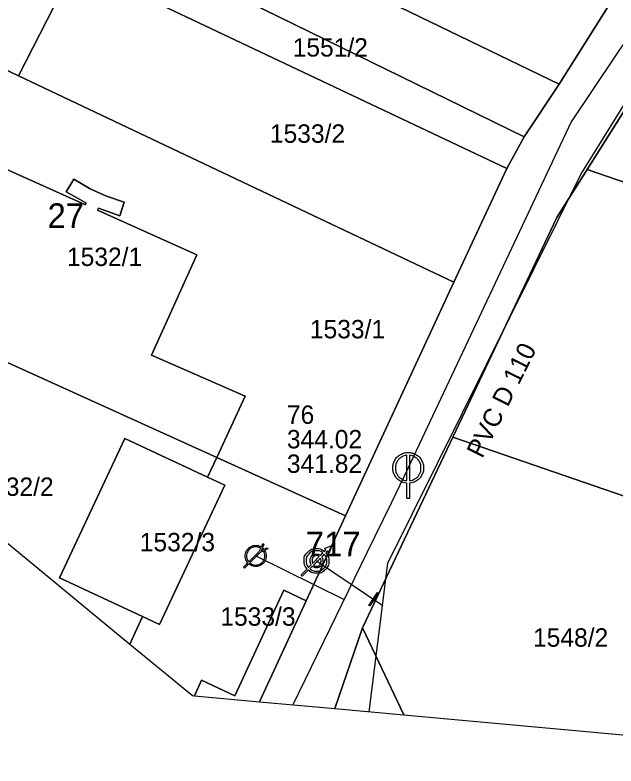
# Model space of a CAD drawing. Extents: x -559813 to -559493, y -1075874 to -1075701.
# Drawn here: x -559758.6 to -559709.6, y -1075858.6 to -1075797.4 of the extents above; entities that cross this region are included whole.
import ezdxf

# ---------------------------------------------------------------- set-up
doc = ezdxf.new("R2010")
doc.units = 0
for name, color, linetype in [('Adresní místo-text', 7, 'Continuous'), ('Armatura vodovodní', 7, 'Continuous'), ('Default', 7, 'Continuous'), ('Kanalizační přípojka', 7, 'Continuous'), ('Kanalizační stoka', 7, 'Continuous'), ('Kanalizační šachta', 7, 'Continuous'), ('Odběrné místo', 7, 'Continuous'), ('Odběrné místo na kanalizaci', 7, 'Continuous'), ('Parcela-polygon', 7, 'Continuous'), ('Parcela-text', 7, 'Continuous'), ('Popis šachty', 7, 'Continuous'), ('Vodovodní přípojka', 7, 'Continuous'), ('Vodovodní řad', 7, 'Continuous'), ('Řad vodovodní popis', 7, 'Continuous')]:
    doc.layers.add(name, color=color, linetype=linetype)

msp = doc.modelspace()

# ---------------------------------------------------------------- linework, layer by layer
at = {"layer": 'Armatura vodovodní'}
msp.add_lwpolyline([(-559729.021, -1075844.533), (-559729.716, -1075845.572), (-559729.781, -1075845.528), (-559729.086, -1075844.49), (-559729.021, -1075844.533)], dxfattribs=at)
at = {"layer": 'Default'}
for points, degree in [([(-559726.683, -1075835.568), (-559726.941, -1075835.55), (-559727.203, -1075835.404), (-559727.5, -1075835.24), (-559727.665, -1075834.943), (-559727.83, -1075834.645), (-559727.83, -1075834.32), (-559727.83, -1075833.993), (-559727.662, -1075833.693), (-559727.493, -1075833.392), (-559727.195, -1075833.231), (-559726.897, -1075833.07), (-559726.58, -1075833.07), (-559726.265, -1075833.07), (-559725.966, -1075833.231), (-559725.667, -1075833.392), (-559725.498, -1075833.693), (-559725.33, -1075833.993), (-559725.33, -1075834.32), (-559725.33, -1075834.645), (-559725.495, -1075834.943), (-559725.66, -1075835.24), (-559725.957, -1075835.404), (-559726.219, -1075835.55), (-559726.477, -1075835.568)], 3), ([(-559726.683, -1075833.282), (-559726.88, -1075833.299), (-559727.095, -1075833.414), (-559727.344, -1075833.549), (-559727.483, -1075833.799), (-559727.622, -1075834.049), (-559727.622, -1075834.32), (-559727.622, -1075834.591), (-559727.486, -1075834.838), (-559727.349, -1075835.084), (-559727.1, -1075835.221), (-559726.888, -1075835.341), (-559726.683, -1075835.355)], 3), ([(-559726.477, -1075835.355), (-559726.272, -1075835.341), (-559726.058, -1075835.221), (-559725.811, -1075835.084), (-559725.674, -1075834.838), (-559725.538, -1075834.591), (-559725.538, -1075834.32), (-559725.538, -1075834.049), (-559725.678, -1075833.799), (-559725.818, -1075833.549), (-559726.067, -1075833.414), (-559726.28, -1075833.299), (-559726.477, -1075833.282)], 3), ([(-559739.665, -1075842.056), (-559739.716, -1075841.995), (-559739.756, -1075841.921), (-559739.87, -1075841.718), (-559739.87, -1075841.496), (-559739.87, -1075841.273), (-559739.755, -1075841.067), (-559739.64, -1075840.862), (-559739.436, -1075840.752), (-559739.232, -1075840.641), (-559739.015, -1075840.641), (-559738.8, -1075840.641), (-559738.596, -1075840.752), (-559738.577, -1075840.762), (-559738.558, -1075840.774)], 3), ([(-559738.609, -1075840.874), (-559738.629, -1075840.861), (-559738.651, -1075840.849), (-559738.829, -1075840.753), (-559739.015, -1075840.753), (-559739.203, -1075840.753), (-559739.38, -1075840.849), (-559739.558, -1075840.945), (-559739.658, -1075841.124), (-559739.757, -1075841.302), (-559739.757, -1075841.496), (-559739.757, -1075841.689), (-559739.659, -1075841.865), (-559739.626, -1075841.924), (-559739.583, -1075841.975)], 3), ([(-559738.294, -1075841.037), (-559738.286, -1075841.051), (-559738.276, -1075841.067), (-559738.161, -1075841.273), (-559738.161, -1075841.496), (-559738.161, -1075841.718), (-559738.273, -1075841.921), (-559738.386, -1075842.125), (-559738.59, -1075842.237), (-559738.793, -1075842.35), (-559739.015, -1075842.35), (-559739.237, -1075842.35), (-559739.44, -1075842.237), (-559739.514, -1075842.197), (-559739.577, -1075842.144)], 3), ([(-559738.464, -1075840.995), (-559738.489, -1075840.968), (-559738.514, -1075840.945)], 2), ([(-559738.463, -1075840.841), (-559738.408, -1075840.887), (-559738.361, -1075840.944)], 2), ([(-559734.832, -1075842.561), (-559735.073, -1075842.284), (-559735.073, -1075841.908), (-559735.073, -1075841.491), (-559734.778, -1075841.196), (-559734.482, -1075840.901), (-559734.063, -1075840.901), (-559733.689, -1075840.901), (-559733.413, -1075841.138)], 3), ([(-559733.531, -1075841.257), (-559733.758, -1075841.068), (-559734.063, -1075841.068), (-559734.413, -1075841.068), (-559734.659, -1075841.314), (-559734.904, -1075841.56), (-559734.904, -1075841.908), (-559734.904, -1075842.215), (-559734.713, -1075842.442)], 3), ([(-559739.496, -1075842.063), (-559739.445, -1075842.106), (-559739.384, -1075842.139), (-559739.207, -1075842.238), (-559739.015, -1075842.238), (-559738.823, -1075842.238), (-559738.646, -1075842.14), (-559738.469, -1075842.042), (-559738.371, -1075841.865), (-559738.273, -1075841.689), (-559738.273, -1075841.496), (-559738.273, -1075841.302), (-559738.373, -1075841.124), (-559738.383, -1075841.105), (-559738.394, -1075841.088)], 3), ([(-559733.305, -1075841.244), (-559733.055, -1075841.525), (-559733.055, -1075841.908), (-559733.055, -1075842.326), (-559733.351, -1075842.62), (-559733.646, -1075842.915), (-559734.063, -1075842.915), (-559734.447, -1075842.915), (-559734.726, -1075842.669)], 3), ([(-559734.607, -1075842.549), (-559734.377, -1075842.747), (-559734.063, -1075842.747), (-559733.716, -1075842.747), (-559733.469, -1075842.501), (-559733.222, -1075842.256), (-559733.222, -1075841.908), (-559733.222, -1075841.594), (-559733.424, -1075841.364)], 3), ([(-559734.493, -1075842.221), (-559734.502, -1075842.205), (-559734.509, -1075842.189), (-559734.571, -1075842.062), (-559734.571, -1075841.92), (-559734.571, -1075841.653), (-559734.427, -1075841.502), (-559734.283, -1075841.35), (-559734.056, -1075841.35), (-559733.908, -1075841.35), (-559733.789, -1075841.421), (-559733.759, -1075841.439), (-559733.734, -1075841.46)], 3), ([(-559733.828, -1075841.554), (-559733.845, -1075841.539), (-559733.864, -1075841.527), (-559733.95, -1075841.474), (-559734.056, -1075841.474), (-559734.206, -1075841.474), (-559734.316, -1075841.577), (-559734.425, -1075841.68), (-559734.425, -1075841.923), (-559734.425, -1075842.034), (-559734.391, -1075842.118)], 3), ([(-559733.633, -1075841.572), (-559733.618, -1075841.596), (-559733.606, -1075841.62), (-559733.543, -1075841.747), (-559733.543, -1075841.908), (-559733.543, -1075842.072), (-559733.609, -1075842.2), (-559733.675, -1075842.329), (-559733.796, -1075842.396), (-559733.917, -1075842.462), (-559734.057, -1075842.462), (-559734.209, -1075842.462), (-559734.328, -1075842.389), (-559734.365, -1075842.366), (-559734.397, -1075842.339)], 3), ([(-559734.304, -1075842.245), (-559734.204, -1075842.34), (-559734.059, -1075842.34), (-559733.897, -1075842.34), (-559733.794, -1075842.227), (-559733.69, -1075842.114), (-559733.69, -1075841.907), (-559733.69, -1075841.776), (-559733.734, -1075841.679), (-559733.735, -1075841.677), (-559733.735, -1075841.676)], 3)]:
    msp.add_open_spline(points, degree=degree, dxfattribs=at)
at = {"layer": 'Kanalizační přípojka'}
msp.add_lwpolyline([(-559739.016, -1075841.496), (-559731.811, -1075845.058)], dxfattribs=at)
at = {"layer": 'Kanalizační stoka'}
for points in [[(-559704.486, -1075792.979), (-559709.634, -1075800.651)], [(-559709.634, -1075800.651), (-559713.29, -1075806.1)], [(-559713.29, -1075806.1), (-559726.58, -1075834.32)], [(-559726.58, -1075834.32), (-559727.976, -1075837.185)], [(-559727.976, -1075837.185), (-559729.959, -1075841.256)], [(-559729.959, -1075841.256), (-559735.99, -1075853.634)]]:
    msp.add_lwpolyline(points, dxfattribs=at)
at = {"layer": 'Kanalizační šachta'}
for points in [[(-559726.683, -1075835.355), (-559726.683, -1075833.282)], [(-559726.477, -1075833.282), (-559726.477, -1075835.355)], [(-559726.477, -1075835.568), (-559726.477, -1075836.82), (-559726.683, -1075836.82), (-559726.683, -1075835.568)]]:
    msp.add_lwpolyline(points, dxfattribs=at)
at = {"layer": 'Odběrné místo'}
for points in [[(-559733.413, -1075841.138), (-559733.285, -1075841.01)], [(-559733.285, -1075841.01), (-559733.403, -1075840.899), (-559732.816, -1075840.658), (-559733.038, -1075841.244), (-559733.175, -1075841.115), (-559733.305, -1075841.244)], [(-559734.391, -1075842.118), (-559733.828, -1075841.554)], [(-559733.735, -1075841.676), (-559734.304, -1075842.245)], [(-559733.734, -1075841.46), (-559733.531, -1075841.257)], [(-559733.424, -1075841.364), (-559733.633, -1075841.572)], [(-559734.713, -1075842.442), (-559734.493, -1075842.221)], [(-559734.726, -1075842.669), (-559735.215, -1075843.158), (-559735.316, -1075843.046), (-559734.832, -1075842.561)], [(-559734.397, -1075842.339), (-559734.607, -1075842.549)]]:
    msp.add_lwpolyline(points, dxfattribs=at)
at = {"layer": 'Odběrné místo na kanalizaci'}
for points in [[(-559739.583, -1075841.975), (-559738.741, -1075841.131), (-559738.609, -1075840.874)], [(-559738.514, -1075840.945), (-559738.563, -1075841.044), (-559738.464, -1075840.995)], [(-559738.558, -1075840.774), (-559738.548, -1075840.755), (-559738.502, -1075840.637), (-559738.442, -1075840.496), (-559738.341, -1075840.542), (-559738.407, -1075840.703), (-559738.455, -1075840.823), (-559738.463, -1075840.841)], [(-559738.361, -1075840.944), (-559738.343, -1075840.935), (-559738.222, -1075840.887), (-559738.072, -1075840.826), (-559738.016, -1075840.92), (-559738.158, -1075840.982), (-559738.276, -1075841.027), (-559738.294, -1075841.037)], [(-559738.394, -1075841.088), (-559738.655, -1075841.222), (-559739.496, -1075842.063)], [(-559739.577, -1075842.144), (-559739.588, -1075842.156), (-559739.678, -1075842.246), (-559739.93, -1075842.497), (-559740.018, -1075842.408), (-559739.766, -1075842.157), (-559739.676, -1075842.068), (-559739.665, -1075842.056)]]:
    msp.add_lwpolyline(points, dxfattribs=at)
at = {"layer": 'Parcela-polygon'}
for p, q in [((-559778.194, -1075824.865), (-559749.276, -1075848.685)), ((-559744.017, -1075852.905), (-559738.719, -1075853.386)), ((-559738.719, -1075853.386), (-559732.551, -1075853.947)), ((-559732.551, -1075853.947), (-559726.935, -1075854.457)), ((-559726.935, -1075854.457), (-559706.34, -1075856.328))]:
    msp.add_line(p, q, dxfattribs=at)
for points in [[(-559732.551, -1075853.947), (-559730.31, -1075847.37), (-559722.94, -1075831.81), (-559714.46, -1075813.89), (-559711.98, -1075809.97), (-559705.24, -1075799.29), (-559698.1, -1075787.99), (-559694.39, -1075782.11), (-559686.19, -1075769.14), (-559684.4, -1075766.45), (-559674.88, -1075752.15), (-559667.58, -1075740.58), (-559681.23, -1075754.03), (-559700.36, -1075780.95), (-559706.7, -1075791.01), (-559714.26, -1075803.02), (-559717.12, -1075807.32), (-559718.54, -1075809.9), (-559722.85, -1075819.18), (-559731.69, -1075838.23), (-559734.91, -1075845.17), (-559738.719, -1075853.386)], [(-559812.545, -1075795.607), (-559773.1, -1075813.33), (-559769.59, -1075805.38), (-559766.53, -1075798.46), (-559758.36, -1075802.33), (-559753.71, -1075793.22), (-559762.4, -1075789.09), (-559800.612, -1075773.14)], [(-559749.276, -1075848.685), (-559748.24, -1075846.45), (-559755.02, -1075843.27), (-559749.7, -1075831.92), (-559742.95, -1075835.07), (-559742.2, -1075833.46), (-559775.35, -1075818.43), (-559778.194, -1075824.865)], [(-559681.019, -1075858.629), (-559676.66, -1075847.75), (-559722.94, -1075831.81), (-559730.31, -1075847.37), (-559726.935, -1075854.457)], [(-559744.017, -1075852.905), (-559743.43, -1075851.64), (-559740.72, -1075852.91), (-559736.71, -1075844.29), (-559734.91, -1075845.17), (-559731.69, -1075838.23), (-559742.2, -1075833.46), (-559742.95, -1075835.07), (-559741.54, -1075835.73), (-559746.86, -1075847.1), (-559748.24, -1075846.45), (-559749.276, -1075848.685)], [(-559738.719, -1075853.386), (-559734.91, -1075845.17), (-559736.71, -1075844.29), (-559740.72, -1075852.91), (-559743.43, -1075851.64), (-559744.017, -1075852.905)], [(-559726.935, -1075854.457), (-559730.31, -1075847.37), (-559732.551, -1075853.947)], [(-559749.276, -1075848.685), (-559744.17, -1075852.891), (-559744.017, -1075852.905)]]:
    msp.add_lwpolyline(points, dxfattribs=at)
for points in [[(-559737.63, -1075771.45), (-559743.97, -1075773.56), (-559749.98, -1075785.74), (-559714.26, -1075803.02), (-559706.7, -1075791.01), (-559707.59, -1075786.09)], [(-559749.98, -1075785.74), (-559752.15, -1075790.16), (-559717.12, -1075807.32), (-559714.26, -1075803.02)], [(-559717.12, -1075807.32), (-559752.15, -1075790.16), (-559753.71, -1075793.22), (-559718.54, -1075809.9)], [(-559753.71, -1075793.22), (-559758.36, -1075802.33), (-559722.85, -1075819.18), (-559718.54, -1075809.9)], [(-559752.88, -1075812.71), (-559754.47, -1075811.8), (-559753.84, -1075810.76), (-559752.51, -1075811.55), (-559751.19, -1075812.16), (-559749.74, -1075812.64), (-559750.1, -1075813.77), (-559751.85, -1075813.14), (-559751.91, -1075813.31), (-559743.83, -1075816.93), (-559747.51, -1075825.13), (-559739.88, -1075828.47), (-559742.2, -1075833.46), (-559731.69, -1075838.23), (-559722.85, -1075819.18), (-559758.36, -1075802.33), (-559766.53, -1075798.46), (-559769.59, -1075805.38), (-559760.42, -1075809.49), (-559752.91, -1075812.86)], [(-559705.24, -1075799.29), (-559711.98, -1075809.97), (-559671.09, -1075824.05), (-559664.87, -1075813.06)], [(-559760.42, -1075809.49), (-559769.59, -1075805.38), (-559773.1, -1075813.33), (-559775.35, -1075818.43), (-559742.2, -1075833.46), (-559739.88, -1075828.47), (-559747.51, -1075825.13), (-559743.83, -1075816.93), (-559751.91, -1075813.31), (-559751.85, -1075813.14), (-559750.1, -1075813.77), (-559749.74, -1075812.64), (-559751.19, -1075812.16), (-559752.51, -1075811.55), (-559753.84, -1075810.76), (-559754.47, -1075811.8), (-559752.88, -1075812.71), (-559752.91, -1075812.86)], [(-559671.09, -1075824.05), (-559711.98, -1075809.97), (-559714.46, -1075813.89), (-559722.94, -1075831.81), (-559676.66, -1075847.75), (-559667.64, -1075825.24)], [(-559755.02, -1075843.27), (-559748.24, -1075846.45), (-559746.86, -1075847.1), (-559741.54, -1075835.73), (-559742.95, -1075835.07), (-559749.7, -1075831.92)]]:
    msp.add_lwpolyline(points, close=True, dxfattribs=at)
at = {"layer": 'Vodovodní přípojka'}
msp.add_line((-559734.064, -1075841.909), (-559728.654, -1075845.531), dxfattribs=at)
at = {"layer": 'Vodovodní řad'}
msp.add_lwpolyline([(-559729.772, -1075854.199), (-559728.25, -1075842.1), (-559720.18, -1075825.84), (-559712.5, -1075810.39), (-559705.929, -1075799.792), (-559700.67, -1075791.31), (-559699.27, -1075788.8), (-559687.46, -1075770.86), (-559674.63, -1075751.91), (-559671.48, -1075746.759)], dxfattribs=at)

# ---------------------------------------------------------------- texts
at = {"layer": 'Adresní místo-text'}
for s, p in [('27', (-559755.993, -1075814.74)), ('717', (-559734.93, -1075841.53))]:
    msp.add_text(s, height=2, dxfattribs=at).set_placement(p)
at = {"layer": 'Parcela-text'}
for s, p in [('1551/2', (-559736, -1075800.77)), ('1533/2', (-559737.86, -1075807.8)), ('1532/1', (-559754.41, -1075817.85)), ('1533/1', (-559734.6, -1075823.75)), ('1532/2', (-559761.63, -1075836.6)), ('1532/3', (-559748.47, -1075841.12)), ('1533/3', (-559741.9, -1075847.19)), ('1548/2', (-559716.4, -1075848.9))]:
    msp.add_text(s, height=1.5, dxfattribs=at).set_placement(p)
at = {"layer": 'Popis šachty'}
for s, p in [('76', (-559736.473, -1075830.724)), ('344.02', (-559736.473, -1075832.724)), ('341.82', (-559736.473, -1075834.724))]:
    msp.add_text(s, height=1.5, dxfattribs=at).set_placement(p)
at = {"layer": 'Řad vodovodní popis'}
msp.add_text('PVC D 110', height=1.5, rotation=63.60433, dxfattribs=at).set_placement((-559720.542, -1075833.608))

doc.saveas('drawing.dxf')
